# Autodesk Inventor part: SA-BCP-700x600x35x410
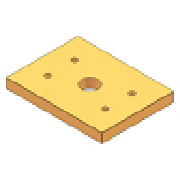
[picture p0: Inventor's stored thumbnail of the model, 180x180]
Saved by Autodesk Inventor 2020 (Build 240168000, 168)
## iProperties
Created: 2019-01
Part Number: SA-BCP-700x600x35x410
Material: S 55 C
Description: Bottom Clamping Plate
Document SubType Name: Modeling
Designer: LENOVO-CADCIM
Standard Revision: 1
Manufacturer: FUTABA
Language: en-US
Size Designation: 700x600x35x410
Categories: <MemberInstance><Categories><Category DisplayName="Mold" InternalName="349578f2-f4d4-4954-8c09-8e99297a61c0" Mnemonic="MOLD"><Category DisplayName="Mold Plates"
Density: 7.85 g/cm^3
Appearance: Orange (Pale)
IsCustomPart: 1
Author: LENOVO-CADCIM
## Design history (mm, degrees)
sketch "Sketch1"
  geometry: L1 (-300, 350)-(300, 350); L2 (300, 350)-(300, -350); L3 (300, -350)-(-300, -350); L4 (-300, -350)-(-300, 350); C1 r 17.5 at (0, 0); 4 further points
  constraints: 8 end point, 2 midpoint, 2 parallel, 1 centre point, 1 coincident, 1 horizontal, 1 horizontal alignment, 1 perpendicular, 1 vertical alignment
  dimensions: "d72" = 600 distance between parallel lines of L2 L4 (= W_); "d73" = 700 distance between parallel lines of L3 L1 (= L); "d74" = 35 diameter of C1 (= dB); "d75" = 205 horizontal distance of point (0, 0) point (-205, 243) (= 0.5 x S1_W); "d76" = 243 vertical distance of point (0, 0) point (-205, 243) (= 0.5 x S1_L)
body "Solid1"
extrude "Extrusion1" new body sketch "Sketch1" distance "d77" = 35 (= H_); taper "d78" = 0 deg
hole "Hole1" sketch "Sketch1" diameter "d79" = 18 (= S1_d1); stored, may be unused: countersink angle "d83" = 90 deg, drill point angle "d85" = 0 deg; dims "d80" = 6, "d81" = 26 (= S1_d2), "d82" = 17.5 (= S1_k), "d84" = 35 (= H_)
pattern_linear "Rectangular Pattern1" dims "d88" = 243 (computed from S1_L, Ns), "d91" = 410 (computed from S1_W, Nw)
extrude "Extrusion2" cut sketch "Sketch1" distance "d92" = 35 (= H_); taper "d93" = 0 deg
chamfer "Chamfer1" distance "d94" = 0.5; stored, may be unused: second distance "d95" = 2, angle "d96" = 45 deg
other parameters: "L" = 700 [user parameter; used in 1 equation term], "W_" = 600 [user parameter; used in 1 equation term], "H_" = 35 [user parameter; used in 3 equation terms], "S1_d1" = 18 [user parameter; used in 1 equation term], "S1_d2" = 26 [user parameter; used in 1 equation term], "S1_k" = 17.5 [user parameter; used in 1 equation term], "S1_L" = 486 [user parameter; used in 2 equation terms], "dB" = 35 [user parameter; used in 1 equation term]
